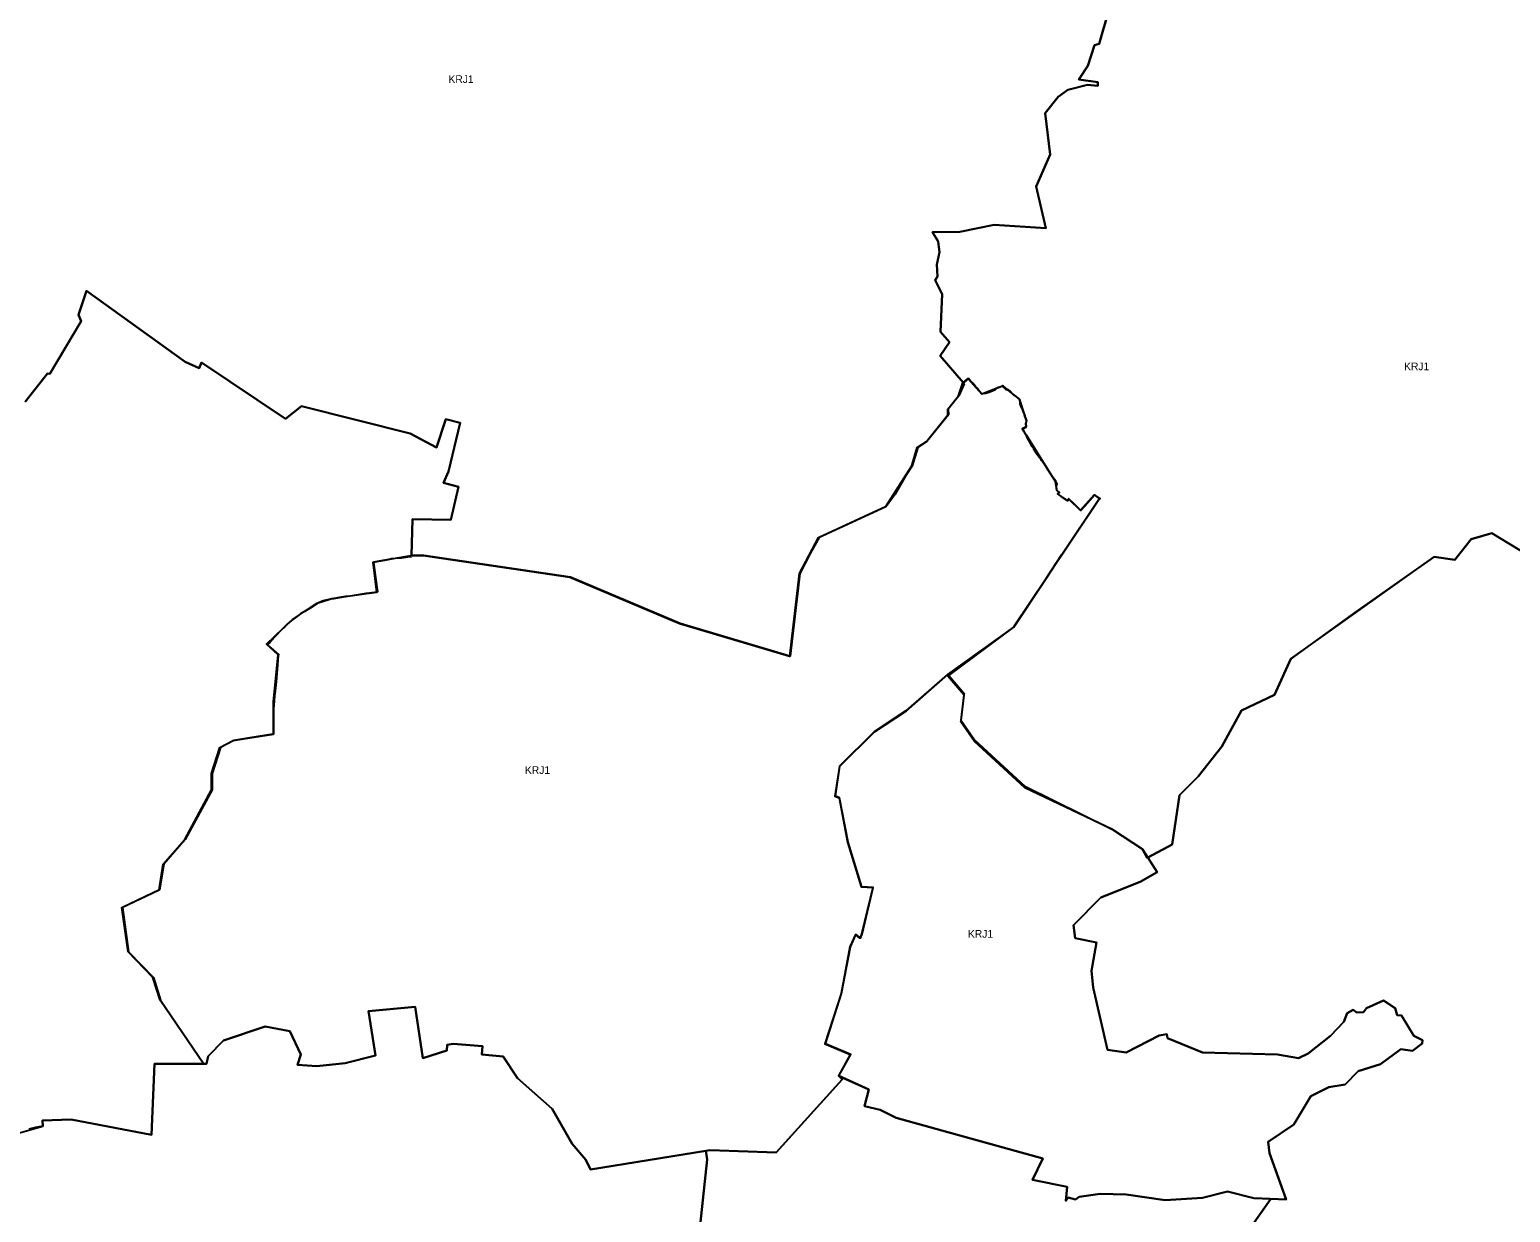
# Model space of a CAD drawing. Extents: x -563112 to -465432, y -1206259 to -1132144.
# Drawn here: x -530418 to -520780, y -1155437 to -1147738 of the extents above; entities that cross this region are included whole.
import ezdxf

# ---------------------------------------------------------------- set-up
doc = ezdxf.new("R2010")
doc.units = 0
doc.layers.add('krajiny', color=7, linetype='Continuous')

msp = doc.modelspace()

# ---------------------------------------------------------------- linework, layer by layer
at = {"layer": 'krajiny'}
for points in [[(-523393.51, -1147611.56), (-523456.81, -1147831.89), (-523488.17, -1147840.17), (-523529.85, -1147975.04), (-523588.3, -1148063.36), (-523465.96, -1148079.44), (-523465.36, -1148103.8), (-523533.63, -1148098.57), (-523659.89, -1148130.5), (-523723.37, -1148175.28), (-523808.28, -1148282.49), (-523775.68, -1148551.52), (-523867.18, -1148758.51), (-523803.11, -1149030.73), (-524140.39, -1149008.96), (-524364.08, -1149053.77), (-524542.07, -1149057.01), (-524504.89, -1149116.99), (-524495.55, -1149186.61), (-524512.86, -1149266.22), (-524508.74, -1149344.76), (-524524.15, -1149369.71), (-524477.98, -1149461.01), (-524489.47, -1149705.6), (-524431.36, -1149773.08), (-524490.88, -1149862.29), (-524341.96, -1150036.25), (-524340.6, -1150037.84), (-524335.14, -1150044.22), (-524369.35, -1150122.68), (-524439.25, -1150208.79), (-524438.47, -1150245.61), (-524578.05, -1150418.32), (-524637.24, -1150458.32), (-524673.23, -1150576.84), (-524714.1, -1150640.26), (-524784.19, -1150762.71), (-524842.66, -1150841.95), (-525279.47, -1151043.21), (-525336.76, -1151149.12), (-525404.91, -1151277.77), (-525468.02, -1151817), (-525471.15, -1151816.07), (-526184.09, -1151603.59), (-526897.74, -1151302.05), (-527852.62, -1151161.33), (-527932.19, -1151161.01), (-527925.46, -1150924.77), (-527677.12, -1150929.38), (-527627.38, -1150713.35), (-527724.5, -1150687.38), (-527691.16, -1150613.98), (-527615.23, -1150297.35), (-527709.93, -1150274.86), (-527770.41, -1150459.25), (-527940.17, -1150367.19), (-528647.67, -1150188.47), (-528751.8, -1150271.82), (-529298.77, -1149904.46), (-529314.57, -1149942.54), (-529405.58, -1149900.33), (-530048.63, -1149438.74), (-530099.98, -1149594.62), (-530083.25, -1149636.94), (-530286.09, -1149978.23), (-530302.11, -1149977.02), (-530447.38, -1150160.23)], [(-520679.31, -1151149.55), (-520900.75, -1151015.3), (-521034.95, -1151055.57), (-521142.31, -1151189.82), (-521276.52, -1151169.68), (-521477.82, -1151310.64), (-521793.2, -1151532.15), (-522209.23, -1151834.21), (-522316.59, -1152069.15), (-522531.32, -1152169.84), (-522658.81, -1152404.77), (-522813.15, -1152599.43), (-522933.93, -1152720.26), (-522980.9, -1153042.45), (-523140.49, -1153127.48), (-523145.3, -1153130.04), (-523175.5, -1153072.18), (-523370.09, -1152944.69), (-523940.46, -1152673.75), (-524269.26, -1152371.79), (-524356.49, -1152244.3), (-524355.41, -1152234.98), (-524336.36, -1152069.83), (-524337.47, -1152068.54), (-524441.75, -1151947.45), (-524436.03, -1151943.2), (-524012.07, -1151628.26), (-523802.45, -1151310.44), (-523700.48, -1151155.84), (-523459.25, -1150793.99), (-523455.63, -1150792.62), (-523451.29, -1150790.97), (-523453.72, -1150789.55), (-523456.56, -1150787.9), (-523473.54, -1150776.89), (-523477.68, -1150773.57), (-523482.59, -1150769.61), (-523485.09, -1150767.23), (-523486.38, -1150768.59), (-523505.65, -1150788.96), (-523532.68, -1150820.03), (-523576.04, -1150869), (-523577.74, -1150867.29), (-523578.33, -1150866.7), (-523600.6, -1150843.78), (-523616.94, -1150827.76), (-523651.64, -1150793.78), (-523654.04, -1150793.29), (-523656.09, -1150792.65), (-523657.99, -1150797.79), (-523660.93, -1150805.74), (-523662.92, -1150804.35), (-523663.03, -1150804.28), (-523670.62, -1150799.58), (-523687.96, -1150788.85), (-523690.98, -1150786.98), (-523695.15, -1150783.74), (-523717.53, -1150766.39), (-523719.11, -1150765.11), (-523724.1, -1150760.9), (-523715.38, -1150750.57), (-523727.17, -1150739.38), (-523731.64, -1150735.65), (-523732.75, -1150729.2), (-523734.73, -1150717.66), (-523734.26, -1150715.44), (-523731.35, -1150702.11), (-523729.97, -1150695.74), (-523739.94, -1150676.93), (-523756.32, -1150656.13), (-523756.85, -1150655.46), (-523757.89, -1150653.64), (-523767.48, -1150636.95), (-523772.91, -1150628.83), (-523777.74, -1150622.24), (-523791.8, -1150603.03), (-523795.03, -1150595.6), (-523796.32, -1150593.76), (-523811.52, -1150570.27), (-523831.36, -1150542.24), (-523835.16, -1150537.31), (-523839.97, -1150530.52), (-523844.2, -1150524.57), (-523857.64, -1150505.9), (-523882.98, -1150468.52), (-523882.47, -1150467.92), (-523893.37, -1150451.26), (-523899.3, -1150440.34), (-523907.54, -1150424.36), (-523923.05, -1150397.36), (-523932.73, -1150376.93), (-523934.73, -1150372.71), (-523954.24, -1150337.76), (-523939.16, -1150328.41), (-523932.3, -1150326.25), (-523930.71, -1150314.5), (-523934.08, -1150310.53), (-523934.45, -1150310.09), (-523934.81, -1150308.98), (-523933.6, -1150303.41), (-523933.31, -1150302.29), (-523932.01, -1150297.22), (-523928.15, -1150281.6), (-523929.39, -1150277.63), (-523930.89, -1150272.87), (-523935.95, -1150265.26), (-523937.56, -1150262.98), (-523938.6, -1150261.52), (-523940.18, -1150255.59), (-523940.89, -1150252.94), (-523942.63, -1150246.48), (-523945.14, -1150237.67), (-523948.28, -1150229.29), (-523951.18, -1150221.91), (-523953.69, -1150214.97), (-523956.07, -1150208.69), (-523959.46, -1150201.54), (-523961.86, -1150196.46), (-523964.46, -1150190.93), (-523968.89, -1150181.53), (-523970.35, -1150178.43), (-523970.79, -1150170.4), (-523971.13, -1150164.44), (-523971.52, -1150160.56), (-523971.69, -1150158.9), (-523972.25, -1150153.34), (-523972.54, -1150150.4), (-523973.01, -1150146.3), (-523978.64, -1150140.57), (-523982.89, -1150136.23), (-523989.57, -1150130.12), (-523997.8, -1150125.9), (-524001.24, -1150124.81), (-524005.32, -1150122.26), (-524009.27, -1150118.97), (-524010.57, -1150117.96), (-524016.9, -1150113.07), (-524020.73, -1150110.15), (-524025.97, -1150106.24), (-524026.53, -1150104.79), (-524028.22, -1150100.4), (-524028.6, -1150099.22), (-524034.77, -1150094.85), (-524038.4, -1150092.38), (-524040.72, -1150090.18), (-524043.47, -1150087.03), (-524046.51, -1150083.64), (-524048.27, -1150081.76), (-524053.38, -1150082.62), (-524057.52, -1150083.32), (-524061.23, -1150082.2), (-524068.48, -1150075.88), (-524074.29, -1150070.68), (-524076.25, -1150066.89), (-524078.91, -1150061.54), (-524081.17, -1150057.01), (-524083.34, -1150057.88), (-524111.83, -1150069.29), (-524113.25, -1150067.88), (-524115.09, -1150066.04), (-524120.09, -1150070.45), (-524136.57, -1150085.01), (-524168.39, -1150098.02), (-524194.69, -1150106.86), (-524219.44, -1150109.1), (-524220.47, -1150108.27), (-524223.06, -1150106.16), (-524225.99, -1150103.79), (-524251.87, -1150072.59), (-524260.99, -1150060.81), (-524280.01, -1150039.63), (-524295.76, -1150022.21), (-524306.97, -1150009.29), (-524308.61, -1150010.57), (-524308.88, -1150010.8), (-524340.6, -1150037.84), (-524341.96, -1150036.25), (-524490.88, -1149862.29), (-524431.36, -1149773.08), (-524489.47, -1149705.6), (-524477.98, -1149461.01), (-524524.15, -1149369.71), (-524508.74, -1149344.76), (-524512.86, -1149266.22), (-524495.55, -1149186.61), (-524504.89, -1149116.99), (-524542.07, -1149057.01), (-524364.08, -1149053.77), (-524140.39, -1149008.96), (-523803.11, -1149030.73), (-523867.18, -1148758.51), (-523775.68, -1148551.52), (-523808.28, -1148282.49), (-523723.37, -1148175.28), (-523659.89, -1148130.5), (-523533.63, -1148098.57), (-523465.36, -1148103.8), (-523465.96, -1148079.44), (-523588.3, -1148063.36), (-523529.85, -1147975.04), (-523488.17, -1147840.17), (-523456.81, -1147831.89), (-523393.51, -1147611.56)], [(-530447.38, -1150160.23), (-530302.11, -1149977.02), (-530286.09, -1149978.23), (-530083.25, -1149636.94), (-530099.98, -1149594.62), (-530048.63, -1149438.74), (-529405.58, -1149900.33), (-529314.57, -1149942.54), (-529298.77, -1149904.46), (-528751.8, -1150271.82), (-528647.67, -1150188.47), (-527940.17, -1150367.19), (-527770.41, -1150459.25), (-527709.93, -1150274.86), (-527615.23, -1150297.35), (-527691.16, -1150613.98), (-527724.5, -1150687.38), (-527627.38, -1150713.35), (-527677.12, -1150929.38), (-527925.46, -1150924.77), (-527932.19, -1151161.01), (-527934.75, -1151169.95), (-527941.98, -1151170.42), (-527997.9, -1151177.66), (-528038.18, -1151180.55), (-528062.8, -1151183.53), (-528068.13, -1151184.17), (-528106.25, -1151191.21), (-528179.57, -1151204.74), (-528179.36, -1151207.07), (-528166.3, -1151303.61), (-528154.03, -1151397.68), (-528155.08, -1151399.4), (-528156.19, -1151399.55), (-528207.26, -1151406.56), (-528228.85, -1151409.53), (-528240.9, -1151411.49), (-528332.54, -1151426.39), (-528362.04, -1151429.22), (-528391.26, -1151432.03), (-528438.6, -1151440.43), (-528453.86, -1151443.14), (-528470.8, -1151447.48), (-528489.07, -1151452.17), (-528507.23, -1151456.73), (-528523.65, -1151462.98), (-528533.96, -1151467.52), (-528542.34, -1151471.2), (-528591.25, -1151503.79), (-528628.65, -1151525.65), (-528651.85, -1151539.21), (-528674.76, -1151555.87), (-528704.3, -1151577.36), (-528726.87, -1151595.9), (-528740.82, -1151607.36), (-528759.92, -1151627.18), (-528767.58, -1151634.95), (-528778.61, -1151646.13), (-528821.66, -1151690.65), (-528844, -1151713.63), (-528857.36, -1151731.17), (-528864.46, -1151736.35), (-528866.47, -1151736.84), (-528871.95, -1151738.16), (-528865.78, -1151744.46), (-528848.75, -1151761.84), (-528796.31, -1151808.34), (-528798.57, -1151810.84), (-528799.88, -1151812.33), (-528806.57, -1151900.43), (-528812.8, -1151983.29), (-528822.94, -1152062.72), (-528823.29, -1152067.3), (-528823.54, -1152070.26), (-528827.23, -1152111.57), (-528827.32, -1152112.77), (-528828.15, -1152131.38), (-528829.62, -1152165.41), (-528829.62, -1152166.78), (-528830.62, -1152241.04), (-528830.75, -1152244.28), (-528830.81, -1152245.92), (-528831, -1152253.89), (-528830.81, -1152271.18), (-528830.85, -1152284.22), (-528830.82, -1152296.51), (-528830.76, -1152321.09), (-528830.86, -1152324.79), (-528834.29, -1152324.61), (-528983.95, -1152348.25), (-529089.25, -1152364.88), (-529176.47, -1152411.86), (-529230.15, -1152579.65), (-529230.15, -1152687.04), (-529404.59, -1153009.2), (-529545.49, -1153170.28), (-529572.33, -1153338.07), (-529813.87, -1153452.17), (-529773.61, -1153740.77), (-529612.59, -1153908.56), (-529565.62, -1154056.22), (-529283.34, -1154469.32), (-529286.58, -1154469.32), (-529605.12, -1154469.32), (-529625.22, -1154931.79), (-530147.83, -1154831.25), (-530334.25, -1154839.36), (-530332.64, -1154876.33), (-530378.68, -1154883.52), (-530422.93, -1154895.16)], [(-523236.73, -1156623.37), (-522339.3, -1155348.96), (-522240.68, -1155353.97), (-522348.05, -1155051.43), (-522356.85, -1154977.65), (-522189.69, -1154864.94), (-522079.39, -1154680.99), (-521961.91, -1154620.98), (-521856.42, -1154605.35), (-521770.09, -1154518.54), (-521625.89, -1154472.6), (-521493.12, -1154375.46), (-521417.25, -1154385.56), (-521354.87, -1154338.23), (-521351.54, -1154316.72), (-521408.76, -1154286.79), (-521489.5, -1154155.42), (-521517.67, -1154153.24), (-521530.42, -1154107.17), (-521605.89, -1154058.21), (-521717.84, -1154107.03), (-521736.48, -1154134.68), (-521780.71, -1154135.77), (-521802.75, -1154117.52), (-521841.89, -1154140.76), (-521864.07, -1154197.69), (-521950.47, -1154286.86), (-522097.28, -1154402.17), (-522159.88, -1154432.95), (-522296.32, -1154408.45), (-522783.66, -1154395.4), (-523011.39, -1154303.27), (-523015.68, -1154277.65), (-523066.01, -1154285.93), (-523281.4, -1154395.36), (-523403.38, -1154379.5), (-523496.81, -1153974.23), (-523507.42, -1153865.67), (-523473.33, -1153680.41), (-523612.1, -1153652.43), (-523623.46, -1153567.21), (-523445.76, -1153387.01), (-523189.42, -1153286.02), (-523080.06, -1153222.91), (-523140.49, -1153127.48), (-522980.9, -1153042.45), (-522933.93, -1152720.26), (-522813.15, -1152599.43), (-522658.81, -1152404.77), (-522531.32, -1152169.84), (-522316.59, -1152069.15), (-522209.23, -1151834.21), (-521276.52, -1151169.68), (-521142.31, -1151189.82), (-521034.95, -1151055.57), (-520900.75, -1151015.3), (-520679.31, -1151149.55)], [(-530497.97, -1154923.7), (-530332.64, -1154876.33), (-530334.25, -1154839.36), (-530147.83, -1154831.25), (-529625.22, -1154931.79), (-529605.12, -1154469.32), (-529286.58, -1154469.32), (-529283.34, -1154469.32), (-529266.65, -1154469.32), (-529256.6, -1154419.05), (-529156.09, -1154318.52), (-528884.74, -1154228.03), (-528723.93, -1154258.2), (-528653.58, -1154409), (-528674.62, -1154475.66), (-528547.74, -1154485.53), (-528363.76, -1154465.15), (-528166.7, -1154416.1), (-528211.54, -1154126.33), (-527908.08, -1154098.12), (-527857.84, -1154432.67), (-527703, -1154383.91), (-527699.35, -1154345.65), (-527660.5, -1154340.52), (-527470.45, -1154355.94), (-527473.64, -1154408.43), (-527335.04, -1154422.25), (-527242.11, -1154563.85), (-527017.22, -1154762.66), (-526886.17, -1154990.66), (-526797.92, -1155095.6), (-526767.81, -1155156.7), (-526016.11, -1155036.46), (-526007.12, -1155092.65), (-526097.57, -1155927.1)], [(-526097.57, -1155927.1), (-526007.12, -1155092.65), (-526016.11, -1155036.46), (-525990.26, -1155032.33), (-525987.03, -1155032.43), (-525558.11, -1155046.49), (-525129.52, -1154571.82), (-525124.43, -1154560.71), (-524956.62, -1154637.63), (-524984.12, -1154746.31), (-524881.55, -1154769.63), (-524778.67, -1154821.05), (-523824.45, -1155087.2), (-523890.39, -1155224.71), (-523664.92, -1155270), (-523674.49, -1155361.67), (-523658.24, -1155339.5), (-523610.36, -1155353.33), (-523586.6, -1155335.54), (-523451.21, -1155316.88), (-523281.79, -1155321.29), (-523026.6, -1155357.65), (-522784.67, -1155342.73), (-522622.54, -1155300.09), (-522449.64, -1155343.35), (-522339.3, -1155348.96), (-523236.73, -1156623.37)]]:
    msp.add_lwpolyline(points, dxfattribs=at)
for points in [[(-524308.88, -1150010.8), (-524222.68, -1150109.1), (-524220.47, -1150108.27), (-524120.09, -1150070.45), (-524113.25, -1150067.88), (-524084.4, -1150057.01), (-524083.34, -1150057.88), (-524078.91, -1150061.54), (-524053.38, -1150082.62), (-524026.53, -1150104.79), (-524010.57, -1150117.96), (-523976.25, -1150146.3), (-523971.52, -1150160.56), (-523951.17, -1150221.93), (-523940.89, -1150252.94), (-523937.56, -1150262.98), (-523931.39, -1150281.6), (-523933.31, -1150302.29), (-523934.08, -1150310.53), (-523935.54, -1150326.25), (-523957.48, -1150337.76), (-523932.73, -1150376.93), (-523777.74, -1150622.24), (-523757.89, -1150653.64), (-523756.32, -1150656.13), (-523743.18, -1150676.93), (-523734.88, -1150735.65), (-523718.61, -1150750.57), (-523727.34, -1150760.9), (-523695.15, -1150783.74), (-523687.96, -1150788.85), (-523664.16, -1150805.74), (-523663.03, -1150804.28), (-523657.99, -1150797.79), (-523654.88, -1150793.78), (-523579.27, -1150869), (-523577.74, -1150867.29), (-523488.32, -1150767.23), (-523486.38, -1150768.59), (-523454.53, -1150790.97), (-523455.63, -1150792.62), (-523802.45, -1151310.44), (-524015.31, -1151628.26), (-524444.98, -1151936.56), (-524714.24, -1152173.11), (-524922.24, -1152309.11), (-525147.27, -1152532.77), (-525176.68, -1152728.06), (-525149.62, -1152739.45), (-525094.12, -1153027.77), (-525005.68, -1153318.44), (-524930.13, -1153322.25), (-525003.21, -1153625.96), (-525012.93, -1153650.53), (-525013.74, -1153652.57), (-525041.11, -1153629.6), (-525043.47, -1153627.62), (-525079.45, -1153708.94), (-525136.26, -1154012.49), (-525242.23, -1154340.56), (-525077, -1154408.47), (-525153.71, -1154548.77), (-525129.52, -1154571.82), (-525558.11, -1155046.49), (-525990.26, -1155032.33), (-526016.11, -1155036.46), (-526767.81, -1155156.7), (-526797.92, -1155095.6), (-526886.17, -1154990.66), (-527017.22, -1154762.66), (-527242.11, -1154563.85), (-527335.04, -1154422.25), (-527473.64, -1154408.43), (-527470.45, -1154355.94), (-527660.5, -1154340.52), (-527699.35, -1154345.65), (-527703, -1154383.91), (-527857.84, -1154432.67), (-527908.08, -1154098.12), (-528211.54, -1154126.33), (-528166.7, -1154416.1), (-528363.76, -1154465.15), (-528547.74, -1154485.53), (-528674.62, -1154475.66), (-528653.58, -1154409), (-528723.93, -1154258.2), (-528884.74, -1154228.03), (-529156.09, -1154318.52), (-529256.6, -1154419.05), (-529266.65, -1154469.32), (-529283.34, -1154469.32), (-529286.58, -1154469.32), (-529568.86, -1154056.22), (-529615.82, -1153908.56), (-529776.85, -1153740.77), (-529817.11, -1153452.17), (-529575.57, -1153338.07), (-529548.73, -1153170.28), (-529407.83, -1153009.2), (-529233.39, -1152687.04), (-529233.39, -1152579.65), (-529179.71, -1152411.86), (-529092.49, -1152364.88), (-528983.95, -1152348.25), (-528830.86, -1152324.79), (-528830.82, -1152296.51), (-528830.75, -1152244.28), (-528830.56, -1152112.77), (-528799.55, -1151808.34), (-528875.19, -1151738.16), (-528767.58, -1151634.95), (-528726.87, -1151595.9), (-528707.54, -1151577.36), (-528674.76, -1151555.87), (-528628.65, -1151525.65), (-528545.58, -1151471.2), (-528533.96, -1151467.52), (-528470.8, -1151447.48), (-528457.1, -1151443.14), (-528438.6, -1151440.43), (-528362.04, -1151429.22), (-528240.9, -1151411.49), (-528207.26, -1151406.56), (-528158.32, -1151399.4), (-528182.81, -1151204.74), (-528106.25, -1151191.21), (-528062.8, -1151183.53), (-527935.43, -1151161.01), (-527932.19, -1151161.02), (-527855.86, -1151161.33), (-526900.98, -1151302.05), (-526187.33, -1151603.59), (-525471.26, -1151817), (-525471.15, -1151816.07), (-525408.15, -1151277.77), (-525282.71, -1151043.21), (-524845.9, -1150841.95), (-524676.47, -1150576.84), (-524640.48, -1150458.32), (-524581.29, -1150418.32), (-524441.71, -1150245.61), (-524442.49, -1150208.79), (-524372.59, -1150122.68), (-524343.84, -1150037.84), (-524341.96, -1150036.25), (-524310.21, -1150009.29)], [(-523612.1, -1153652.43), (-523473.33, -1153680.41), (-523507.42, -1153865.67), (-523496.81, -1153974.23), (-523403.38, -1154379.5), (-523281.4, -1154395.36), (-523066.01, -1154285.93), (-523015.68, -1154277.65), (-523011.39, -1154303.27), (-522783.66, -1154395.4), (-522296.32, -1154408.45), (-522159.88, -1154432.95), (-522097.28, -1154402.17), (-521950.47, -1154286.86), (-521864.07, -1154197.69), (-521841.89, -1154140.76), (-521802.75, -1154117.52), (-521780.71, -1154135.77), (-521736.48, -1154134.68), (-521717.84, -1154107.03), (-521605.89, -1154058.21), (-521530.42, -1154107.17), (-521517.67, -1154153.24), (-521489.5, -1154155.42), (-521408.76, -1154286.79), (-521351.54, -1154316.72), (-521354.87, -1154338.23), (-521417.25, -1154385.56), (-521493.12, -1154375.46), (-521625.89, -1154472.6), (-521770.09, -1154518.54), (-521856.42, -1154605.35), (-521961.91, -1154620.98), (-522079.39, -1154680.99), (-522189.69, -1154864.94), (-522356.85, -1154977.65), (-522348.05, -1155051.43), (-522240.68, -1155353.97), (-522449.64, -1155343.35), (-522622.54, -1155300.09), (-522784.67, -1155342.73), (-523026.6, -1155357.65), (-523281.79, -1155321.29), (-523451.21, -1155316.88), (-523586.6, -1155335.54), (-523610.36, -1155353.33), (-523658.24, -1155339.5), (-523674.49, -1155361.67), (-523664.92, -1155270), (-523890.39, -1155224.71), (-523824.45, -1155087.2), (-524778.67, -1154821.05), (-524881.55, -1154769.63), (-524984.12, -1154746.31), (-524956.62, -1154637.63), (-525150.47, -1154548.77), (-525073.76, -1154408.47), (-525238.99, -1154340.56), (-525133.02, -1154012.49), (-525076.21, -1153708.94), (-525041.11, -1153629.6), (-525040.23, -1153627.62), (-525012.93, -1153650.53), (-525010.5, -1153652.57), (-524999.97, -1153625.96), (-524926.89, -1153322.25), (-525002.44, -1153318.44), (-525090.88, -1153027.77), (-525146.38, -1152739.45), (-525173.44, -1152728.06), (-525144.03, -1152532.77), (-524919, -1152309.11), (-524711, -1152173.11), (-524441.75, -1151936.56), (-524436.03, -1151943.2), (-524336.36, -1152058.95), (-524337.47, -1152068.54), (-524356.49, -1152233.41), (-524355.41, -1152234.98), (-524269.26, -1152360.9), (-523940.46, -1152662.86), (-523370.09, -1152944.69), (-523175.5, -1153072.18), (-523140.49, -1153127.48), (-523080.06, -1153222.91), (-523189.42, -1153286.02), (-523445.76, -1153387.01), (-523623.46, -1153567.21)]]:
    msp.add_lwpolyline(points, close=True, dxfattribs=at)

# ---------------------------------------------------------------- texts
for p in [(-527691.65, -1148085.76), (-521472.1, -1149955.41), (-527194.11, -1152582.99), (-524310.84, -1153649.12)]:
    msp.add_text('KRJ1', height=50, dxfattribs=at).set_placement(p)

doc.saveas('drawing.dxf')
